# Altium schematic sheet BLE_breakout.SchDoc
size A
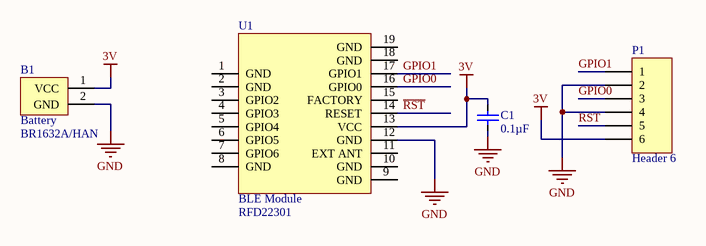
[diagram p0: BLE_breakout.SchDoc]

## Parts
B1  Battery  Manufacturer Part Number: BR1632A/HAN  [Battery_type1]
C1  Capacitance: 0.1µF  [CAPC1608N]  (hidden comment: Cap 0.1µF)
P1  Header 6  [HDR1X6]
U1  BLE Module  Manufacturer Part Number: RFD22301  [BLE_module]

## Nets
3V: B1.1(VCC) C1.2 P1.6 U1.13(VCC)
GND: B1.2(GND) C1.1 P1.2 P1.4 U1.12(GND)
GPIO0: P1.3 U1.16(GPIO0)
GPIO1: P1.1 U1.17(GPIO1)
~{RST}: P1.5 U1.14(RESET)

Not connected (* = marked no-connect by the designer): U1 1(GND) 2(GND) 3(GPIO2) 4(GPIO3) 5(GPIO4) 6(GPIO5) 7(GPIO6) 8(GND) 9(GND) 10(GND) 11(EXT_ANT) 15(FACTORY) 18(GND) 19(GND)

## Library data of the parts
B1 = Battery: Manufacturer: Panasonic; Capacity: 120mAh; Output Voltage: 3V; Chemistry/Technology: Lithium
C1 = Cap 0.1µF: CAP CER 0.1UF 16V X7R 0603; Manufacturer: Yageo; Manufacturer Part Number: CC0603KRX7R7BB104; Tolerance: ±10%
P1 = Header 6: Header, 6-Pin
U1 = BLE Module: Manufacturer: RF Digital; Data Rate: 8Mbps; Frequency: 2.4GHz; Sensitivity: -93dBm; Interface: SPI,UART; Current - Receiving: 12mA; Operating Supply Voltage: 3V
